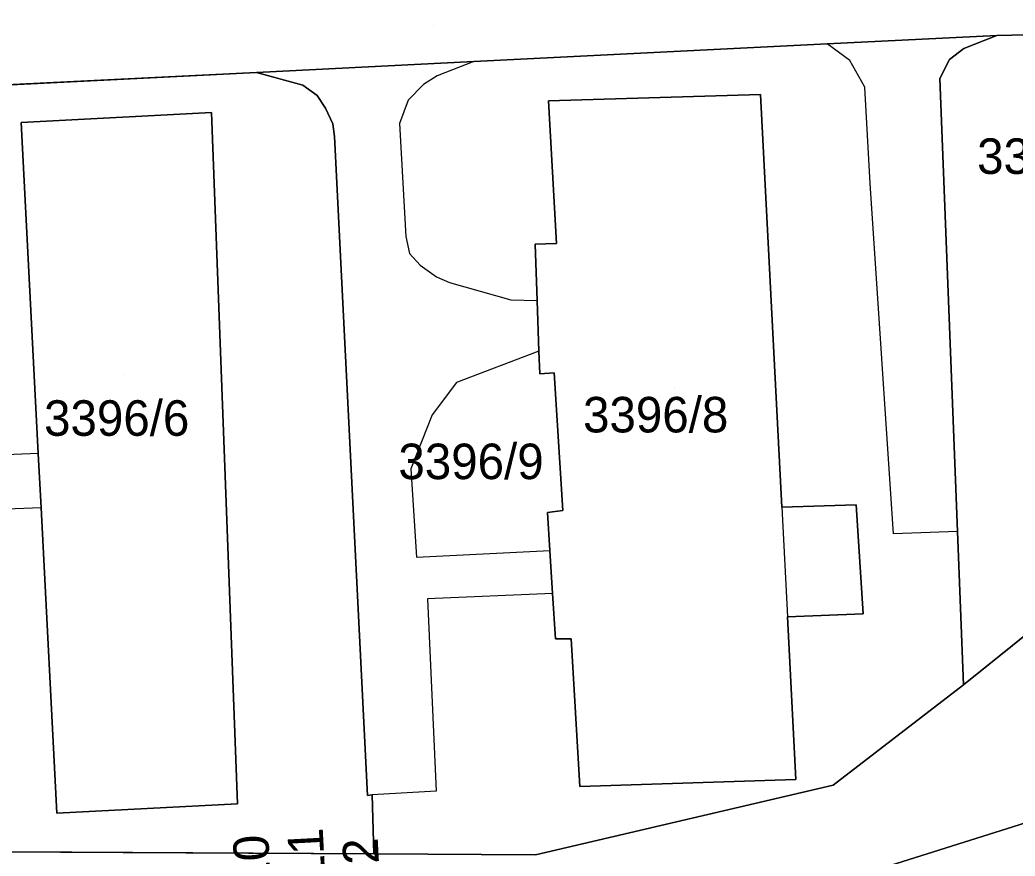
# Model space of a CAD drawing. Extents: x -264070 to -262271, y -1238894 to -1238141.
# Drawn here: x -262648.2 to -262592.1, y -1238480.7 to -1238433.7 of the extents above; entities that cross this region are included whole.
import ezdxf

# ---------------------------------------------------------------- set-up
doc = ezdxf.new("R2010")
doc.units = 0
for name, color, linetype in [('body_kn', 7, 'Continuous'), ('kladpar_druhypozemkov', 7, 'Continuous'), ('kladpar_hranice', 7, 'Continuous'), ('kladpar_parcelnecisla', 7, 'Continuous'), ('kladpar_plochy', 7, 'Continuous'), ('zappar_hrandruhpozemk', 7, 'Continuous')]:
    doc.layers.add(name, color=color, linetype=linetype)

msp = doc.modelspace()

# ---------------------------------------------------------------- linework, layer by layer
at = {"layer": 'body_kn'}
for p, q in [((-262593.16, -1238434.55), (-262593.16, -1238434.55)), ((-262602.72, -1238435.03), (-262602.72, -1238435.03)), ((-262595.02, -1238435.29), (-262595.02, -1238435.29)), ((-262622.62, -1238436.02), (-262622.62, -1238436.02)), ((-262622.62, -1238436.02), (-262622.62, -1238436.02)), ((-262601.45, -1238435.96), (-262601.45, -1238435.96)), ((-262595.84, -1238435.91), (-262595.84, -1238435.91)), ((-262634.86, -1238436.64), (-262634.86, -1238436.64)), ((-262624.69, -1238436.82), (-262624.69, -1238436.82)), ((-262596.37, -1238436.97), (-262596.37, -1238436.97)), ((-262632.24, -1238437.35), (-262632.24, -1238437.35)), ((-262625.46, -1238437.32), (-262625.46, -1238437.32)), ((-262600.6, -1238437.46), (-262600.6, -1238437.46)), ((-262631.44, -1238437.94), (-262631.44, -1238437.94)), ((-262606.47, -1238437.88), (-262606.47, -1238437.88)), ((-262606.47, -1238437.88), (-262606.47, -1238437.88)), ((-262630.97, -1238438.64), (-262630.97, -1238438.64)), ((-262626.32, -1238438.2), (-262626.32, -1238438.2)), ((-262618.41, -1238438.24), (-262618.41, -1238438.24)), ((-262637.39, -1238438.89), (-262637.39, -1238438.89)), ((-262637.39, -1238438.89), (-262637.39, -1238438.89)), ((-262648.1, -1238439.46), (-262648.1, -1238439.46)), ((-262630.56, -1238439.54), (-262630.56, -1238439.54)), ((-262626.81, -1238439.51), (-262626.81, -1238439.51)), ((-262630.46, -1238440.24), (-262630.46, -1238440.24)), ((-262600.31, -1238442.88), (-262600.31, -1238442.88)), ((-262626.44, -1238445.88), (-262626.44, -1238445.88)), ((-262619.16, -1238446.31), (-262619.16, -1238446.31)), ((-262617.97, -1238446.26), (-262617.97, -1238446.26)), ((-262626.23, -1238446.82), (-262626.23, -1238446.82)), ((-262625.64, -1238447.49), (-262625.64, -1238447.49)), ((-262624.72, -1238448.15), (-262624.72, -1238448.15)), ((-262623.98, -1238448.46), (-262623.98, -1238448.46)), ((-262620.54, -1238449.43), (-262620.54, -1238449.43)), ((-262619.05, -1238449.47), (-262619.05, -1238449.47)), ((-262618.95, -1238452.32), (-262618.95, -1238452.32)), ((-262618.95, -1238452.32), (-262618.95, -1238452.32)), ((-262618.91, -1238453.6), (-262618.91, -1238453.6)), ((-262618.09, -1238453.55), (-262618.09, -1238453.55)), ((-262623.6, -1238454.09), (-262623.6, -1238454.09)), ((-262624.97, -1238455.91), (-262624.97, -1238455.91)), ((-262647.14, -1238458.09), (-262647.14, -1238458.09)), ((-262647.14, -1238458.09), (-262647.14, -1238458.09)), ((-262626.17, -1238458.94), (-262626.17, -1238458.94)), ((-262601.08, -1238460.97), (-262601.08, -1238460.97)), ((-262646.98, -1238461.15), (-262646.98, -1238461.15)), ((-262646.98, -1238461.15), (-262646.98, -1238461.15)), ((-262618.47, -1238461.4), (-262618.47, -1238461.4)), ((-262617.61, -1238461.29), (-262617.61, -1238461.29)), ((-262605.28, -1238461.1), (-262605.28, -1238461.1)), ((-262605.28, -1238461.1), (-262605.28, -1238461.1)), ((-262598.98, -1238462.6), (-262598.98, -1238462.6)), ((-262595.38, -1238462.47), (-262595.38, -1238462.47)), ((-262595.38, -1238462.47), (-262595.38, -1238462.47)), ((-262618.33, -1238463.54), (-262618.33, -1238463.54)), ((-262625.84, -1238463.92), (-262625.84, -1238463.92)), ((-262618.18, -1238465.96), (-262618.18, -1238465.96)), ((-262618.18, -1238465.96), (-262618.18, -1238465.96)), ((-262625.22, -1238466.27), (-262625.22, -1238466.27)), ((-262600.7, -1238467.11), (-262600.7, -1238467.11)), ((-262604.96, -1238467.28), (-262604.96, -1238467.28)), ((-262618.01, -1238468.52), (-262618.01, -1238468.52)), ((-262617.13, -1238468.52), (-262617.13, -1238468.52)), ((-262595.04, -1238471.11), (-262595.04, -1238471.11)), ((-262604.49, -1238476.44), (-262604.49, -1238476.44)), ((-262602.39, -1238476.75), (-262602.39, -1238476.75)), ((-262628.35, -1238477.3), (-262628.35, -1238477.3)), ((-262624.74, -1238477.1), (-262624.74, -1238477.1)), ((-262616.65, -1238476.82), (-262616.65, -1238476.82)), ((-262635.92, -1238477.8), (-262635.92, -1238477.8)), ((-262628.6, -1238477.34), (-262628.6, -1238477.34)), ((-262646.1, -1238478.32), (-262646.1, -1238478.32)), ((-262628.25, -1238480.62), (-262628.25, -1238480.62)), ((-262619.15, -1238480.68), (-262619.15, -1238480.68))]:
    msp.add_line(p, q, dxfattribs=at)
at = {"layer": 'kladpar_druhypozemkov'}
for p, q in [((-262624.9, -1238433.98), (-262624.9, -1238433.98)), ((-262642.33, -1238453.65), (-262642.33, -1238453.65)), ((-262611.33, -1238454.45), (-262611.33, -1238454.45)), ((-262622.42, -1238457.46), (-262622.42, -1238457.46))]:
    msp.add_line(p, q, dxfattribs=at)
at = {"layer": 'kladpar_hranice'}
for p, q in [((-262634.86, -1238436.64), (-262622.62, -1238436.02)), ((-262595.04, -1238471.11), (-262575.44, -1238455.34))]:
    msp.add_line(p, q, dxfattribs=at)
for points in [[(-262528.81, -1238443.27), (-262550.25, -1238441.7), (-262558.38, -1238440.81), (-262565.14, -1238438.89), (-262571.97, -1238436.07), (-262583.91, -1238434.36), (-262593.16, -1238434.55), (-262602.72, -1238435.03), (-262622.62, -1238436.02), (-262634.86, -1238436.64), (-262653.53, -1238437.57), (-262663.29, -1238438.06), (-262682.32, -1238439.01), (-262682.26, -1238433.07), (-262681.34, -1238433.03), (-262670.81, -1238432.73), (-262623.19, -1238430.38), (-262610.89, -1238429.75), (-262587.08, -1238428.65)], [(-262622.62, -1238436.02), (-262602.72, -1238435.03), (-262593.16, -1238434.55), (-262595.02, -1238435.29), (-262595.84, -1238435.91), (-262596.37, -1238436.97), (-262595.38, -1238462.47), (-262595.04, -1238471.11), (-262602.39, -1238476.75), (-262619.15, -1238480.68), (-262628.25, -1238480.62), (-262628.35, -1238477.3), (-262628.6, -1238477.34), (-262630.46, -1238440.24), (-262630.56, -1238439.54), (-262630.97, -1238438.64), (-262631.44, -1238437.94), (-262632.24, -1238437.35), (-262634.86, -1238436.64)], [(-262583.91, -1238434.36), (-262582.74, -1238444.64), (-262588.37, -1238445.12), (-262587.13, -1238454.84), (-262583.73, -1238454.53), (-262583.82, -1238453.69), (-262581.76, -1238453.64), (-262581.51, -1238455.92), (-262578.21, -1238455.6), (-262575.44, -1238455.34), (-262595.04, -1238471.11), (-262595.38, -1238462.47), (-262596.37, -1238436.97), (-262595.84, -1238435.91), (-262595.02, -1238435.29), (-262593.16, -1238434.55), (-262583.91, -1238434.36)], [(-262653.53, -1238437.57), (-262634.86, -1238436.64), (-262632.24, -1238437.35), (-262631.44, -1238437.94), (-262630.97, -1238438.64), (-262630.56, -1238439.54), (-262630.46, -1238440.24), (-262628.6, -1238477.34), (-262628.35, -1238477.3), (-262628.25, -1238480.62), (-262658.86, -1238480.45), (-262658.86, -1238477.25), (-262659.07, -1238472.97), (-262659.08, -1238466.87), (-262659.65, -1238466.31), (-262660.03, -1238461.03), (-262660.03, -1238461.01), (-262660.8, -1238441.56), (-262661.93, -1238438.83), (-262663.29, -1238438.06)], [(-262618.41, -1238438.24), (-262617.97, -1238446.26), (-262619.16, -1238446.31), (-262619.05, -1238449.47), (-262618.95, -1238452.32), (-262618.91, -1238453.6), (-262618.09, -1238453.55), (-262617.61, -1238461.29), (-262618.47, -1238461.4), (-262618.33, -1238463.54), (-262618.18, -1238465.96), (-262618.01, -1238468.52), (-262617.13, -1238468.52), (-262616.65, -1238476.82), (-262604.49, -1238476.44), (-262604.96, -1238467.28), (-262600.7, -1238467.11), (-262601.08, -1238460.97), (-262605.28, -1238461.1), (-262606.47, -1238437.88), (-262618.41, -1238438.24)], [(-262606.47, -1238437.88), (-262605.28, -1238461.1), (-262601.08, -1238460.97), (-262600.7, -1238467.11), (-262604.96, -1238467.28), (-262604.49, -1238476.44), (-262616.65, -1238476.82), (-262617.13, -1238468.52), (-262618.01, -1238468.52), (-262618.18, -1238465.96), (-262618.33, -1238463.54), (-262618.47, -1238461.4), (-262617.61, -1238461.29), (-262618.09, -1238453.55), (-262618.91, -1238453.6), (-262618.95, -1238452.32), (-262619.05, -1238449.47), (-262619.16, -1238446.31), (-262617.97, -1238446.26), (-262618.41, -1238438.24), (-262606.47, -1238437.88)], [(-262648.1, -1238439.46), (-262647.14, -1238458.09), (-262646.98, -1238461.15), (-262646.1, -1238478.32), (-262635.92, -1238477.8), (-262637.39, -1238438.89), (-262648.1, -1238439.46)], [(-262637.39, -1238438.89), (-262635.92, -1238477.8), (-262646.1, -1238478.32), (-262646.98, -1238461.15), (-262647.14, -1238458.09), (-262648.1, -1238439.46), (-262637.39, -1238438.89)], [(-262677.42, -1238504.32), (-262685.67, -1238480.03), (-262658.86, -1238480.45), (-262628.25, -1238480.62), (-262619.15, -1238480.68), (-262602.39, -1238476.75), (-262595.04, -1238471.11)], [(-262591.97, -1238490.87), (-262589.9, -1238490.22), (-262580.67, -1238487.33), (-262573.28, -1238485.02), (-262571.25, -1238484.38), (-262563.98, -1238482.11), (-262567.4, -1238471.26), (-262583.94, -1238476.48), (-262602.63, -1238482.36), (-262621.38, -1238488.27), (-262618.01, -1238499.02), (-262610.04, -1238496.52), (-262608.66, -1238496.09), (-262599.27, -1238493.15), (-262591.97, -1238490.87)], [(-262583.94, -1238476.48), (-262580.67, -1238487.33), (-262589.9, -1238490.22), (-262591.97, -1238490.87), (-262599.27, -1238493.15), (-262602.63, -1238482.36), (-262583.94, -1238476.48)]]:
    msp.add_lwpolyline(points, dxfattribs=at)
at = {"layer": 'kladpar_plochy'}
for p, q in [((-262602.72, -1238435.03), (-262593.16, -1238434.55)), ((-262593.16, -1238434.55), (-262595.02, -1238435.29)), ((-262622.62, -1238436.02), (-262602.72, -1238435.03)), ((-262595.02, -1238435.29), (-262595.84, -1238435.91)), ((-262634.86, -1238436.64), (-262622.62, -1238436.02)), ((-262595.84, -1238435.91), (-262596.37, -1238436.97)), ((-262653.53, -1238437.57), (-262634.86, -1238436.64)), ((-262632.24, -1238437.35), (-262634.86, -1238436.64)), ((-262634.86, -1238436.64), (-262632.24, -1238437.35)), ((-262596.37, -1238436.97), (-262595.38, -1238462.47)), ((-262631.44, -1238437.94), (-262632.24, -1238437.35)), ((-262632.24, -1238437.35), (-262631.44, -1238437.94)), ((-262630.97, -1238438.64), (-262631.44, -1238437.94)), ((-262631.44, -1238437.94), (-262630.97, -1238438.64)), ((-262606.47, -1238437.88), (-262618.41, -1238438.24)), ((-262605.28, -1238461.1), (-262606.47, -1238437.88)), ((-262630.56, -1238439.54), (-262630.97, -1238438.64)), ((-262630.97, -1238438.64), (-262630.56, -1238439.54)), ((-262618.41, -1238438.24), (-262617.97, -1238446.26)), ((-262637.39, -1238438.89), (-262648.1, -1238439.46)), ((-262635.92, -1238477.8), (-262637.39, -1238438.89)), ((-262648.1, -1238439.46), (-262647.14, -1238458.09)), ((-262630.46, -1238440.24), (-262630.56, -1238439.54)), ((-262630.56, -1238439.54), (-262630.46, -1238440.24)), ((-262628.6, -1238477.34), (-262630.46, -1238440.24)), ((-262630.46, -1238440.24), (-262628.6, -1238477.34)), ((-262617.97, -1238446.26), (-262619.16, -1238446.31)), ((-262619.16, -1238446.31), (-262619.05, -1238449.47)), ((-262619.05, -1238449.47), (-262618.95, -1238452.32)), ((-262618.95, -1238452.32), (-262618.91, -1238453.6)), ((-262618.91, -1238453.6), (-262618.09, -1238453.55)), ((-262618.09, -1238453.55), (-262617.61, -1238461.29)), ((-262595.04, -1238471.11), (-262575.44, -1238455.34)), ((-262647.14, -1238458.09), (-262646.98, -1238461.15)), ((-262601.08, -1238460.97), (-262605.28, -1238461.1)), ((-262600.7, -1238467.11), (-262601.08, -1238460.97)), ((-262646.98, -1238461.15), (-262646.1, -1238478.32)), ((-262617.61, -1238461.29), (-262618.47, -1238461.4)), ((-262618.47, -1238461.4), (-262618.33, -1238463.54)), ((-262595.38, -1238462.47), (-262595.04, -1238471.11)), ((-262618.33, -1238463.54), (-262618.18, -1238465.96)), ((-262618.18, -1238465.96), (-262618.01, -1238468.52)), ((-262604.96, -1238467.28), (-262600.7, -1238467.11)), ((-262604.49, -1238476.44), (-262604.96, -1238467.28)), ((-262618.01, -1238468.52), (-262617.13, -1238468.52)), ((-262617.13, -1238468.52), (-262616.65, -1238476.82)), ((-262595.04, -1238471.11), (-262602.39, -1238476.75)), ((-262602.39, -1238476.75), (-262595.04, -1238471.11)), ((-262602.39, -1238476.75), (-262619.15, -1238480.68)), ((-262619.15, -1238480.68), (-262602.39, -1238476.75)), ((-262616.65, -1238476.82), (-262604.49, -1238476.44)), ((-262583.94, -1238476.48), (-262602.63, -1238482.36)), ((-262628.35, -1238477.3), (-262628.6, -1238477.34)), ((-262628.6, -1238477.34), (-262628.35, -1238477.3)), ((-262628.25, -1238480.62), (-262628.35, -1238477.3)), ((-262628.35, -1238477.3), (-262628.25, -1238480.62)), ((-262646.1, -1238478.32), (-262635.92, -1238477.8)), ((-262628.25, -1238480.62), (-262658.86, -1238480.45)), ((-262658.86, -1238480.45), (-262628.25, -1238480.62)), ((-262619.15, -1238480.68), (-262628.25, -1238480.62)), ((-262628.25, -1238480.62), (-262619.15, -1238480.68))]:
    msp.add_line(p, q, dxfattribs=at)
msp.add_lwpolyline([(-262528.81, -1238443.27), (-262550.25, -1238441.7), (-262558.38, -1238440.81), (-262565.14, -1238438.89), (-262571.97, -1238436.07), (-262583.91, -1238434.36), (-262593.16, -1238434.55), (-262602.72, -1238435.03), (-262622.62, -1238436.02), (-262634.86, -1238436.64), (-262653.53, -1238437.57)], dxfattribs=at)
for points in [[(-262583.91, -1238434.36), (-262582.74, -1238444.64), (-262588.37, -1238445.12), (-262587.13, -1238454.84), (-262583.73, -1238454.53), (-262583.82, -1238453.69), (-262581.76, -1238453.64), (-262581.51, -1238455.92), (-262578.21, -1238455.6), (-262575.44, -1238455.34), (-262595.04, -1238471.11), (-262595.38, -1238462.47), (-262596.37, -1238436.97), (-262595.84, -1238435.91), (-262595.02, -1238435.29), (-262593.16, -1238434.55)], [(-262606.47, -1238437.88), (-262605.28, -1238461.1), (-262601.08, -1238460.97), (-262600.7, -1238467.11), (-262604.96, -1238467.28), (-262604.49, -1238476.44), (-262616.65, -1238476.82), (-262617.13, -1238468.52), (-262618.01, -1238468.52), (-262618.18, -1238465.96), (-262618.33, -1238463.54), (-262618.47, -1238461.4), (-262617.61, -1238461.29), (-262618.09, -1238453.55), (-262618.91, -1238453.6), (-262618.95, -1238452.32), (-262619.05, -1238449.47), (-262619.16, -1238446.31), (-262617.97, -1238446.26), (-262618.41, -1238438.24)], [(-262637.39, -1238438.89), (-262635.92, -1238477.8), (-262646.1, -1238478.32), (-262646.98, -1238461.15), (-262647.14, -1238458.09), (-262648.1, -1238439.46)], [(-262583.94, -1238476.48), (-262580.67, -1238487.33), (-262589.9, -1238490.22), (-262591.97, -1238490.87), (-262599.27, -1238493.15), (-262602.63, -1238482.36)]]:
    msp.add_lwpolyline(points, close=True, dxfattribs=at)
at = {"layer": 'zappar_hrandruhpozemk'}
for p, q in [((-262626.81, -1238439.51), (-262626.44, -1238445.88)), ((-262598.98, -1238462.6), (-262600.31, -1238442.88)), ((-262618.95, -1238452.32), (-262623.6, -1238454.09)), ((-262623.6, -1238454.09), (-262624.97, -1238455.91)), ((-262647.14, -1238458.09), (-262653.31, -1238458.32)), ((-262646.98, -1238461.15), (-262653.97, -1238461.41)), ((-262605.28, -1238461.1), (-262604.96, -1238467.28)), ((-262595.38, -1238462.47), (-262598.98, -1238462.6)), ((-262625.84, -1238463.92), (-262618.33, -1238463.54)), ((-262618.18, -1238465.96), (-262625.22, -1238466.27))]:
    msp.add_line(p, q, dxfattribs=at)
for points in [[(-262600.31, -1238442.88), (-262600.6, -1238437.46), (-262601.45, -1238435.96), (-262602.72, -1238435.03)], [(-262622.62, -1238436.02), (-262624.69, -1238436.82), (-262625.46, -1238437.32), (-262626.32, -1238438.2), (-262626.81, -1238439.51)], [(-262626.44, -1238445.88), (-262626.23, -1238446.82), (-262625.64, -1238447.49), (-262624.72, -1238448.15), (-262623.98, -1238448.46), (-262620.54, -1238449.43), (-262619.05, -1238449.47)], [(-262624.97, -1238455.91), (-262626.17, -1238458.94), (-262625.84, -1238463.92)], [(-262625.22, -1238466.27), (-262624.74, -1238477.1), (-262628.35, -1238477.3)]]:
    msp.add_lwpolyline(points, dxfattribs=at)

# ---------------------------------------------------------------- texts
at = {"layer": 'kladpar_parcelnecisla'}
for s, p in [('3396/11', (-262594.277, -1238442.35)), ('3396/8', (-262616.468, -1238456.9)), ('3396/6', (-262646.815, -1238457.09)), ('3396/9', (-262626.865, -1238459.53))]:
    msp.add_text(s, height=2, dxfattribs=at).set_placement(p)
for s, p in [('3392/11', (-262630.623, -1238488.784)), ('3392/10', (-262633.69, -1238489.154)), ('3392/12', (-262627.527, -1238489.329))]:
    msp.add_text(s, height=2, rotation=93, dxfattribs=at).set_placement(p)

doc.saveas('drawing.dxf')
